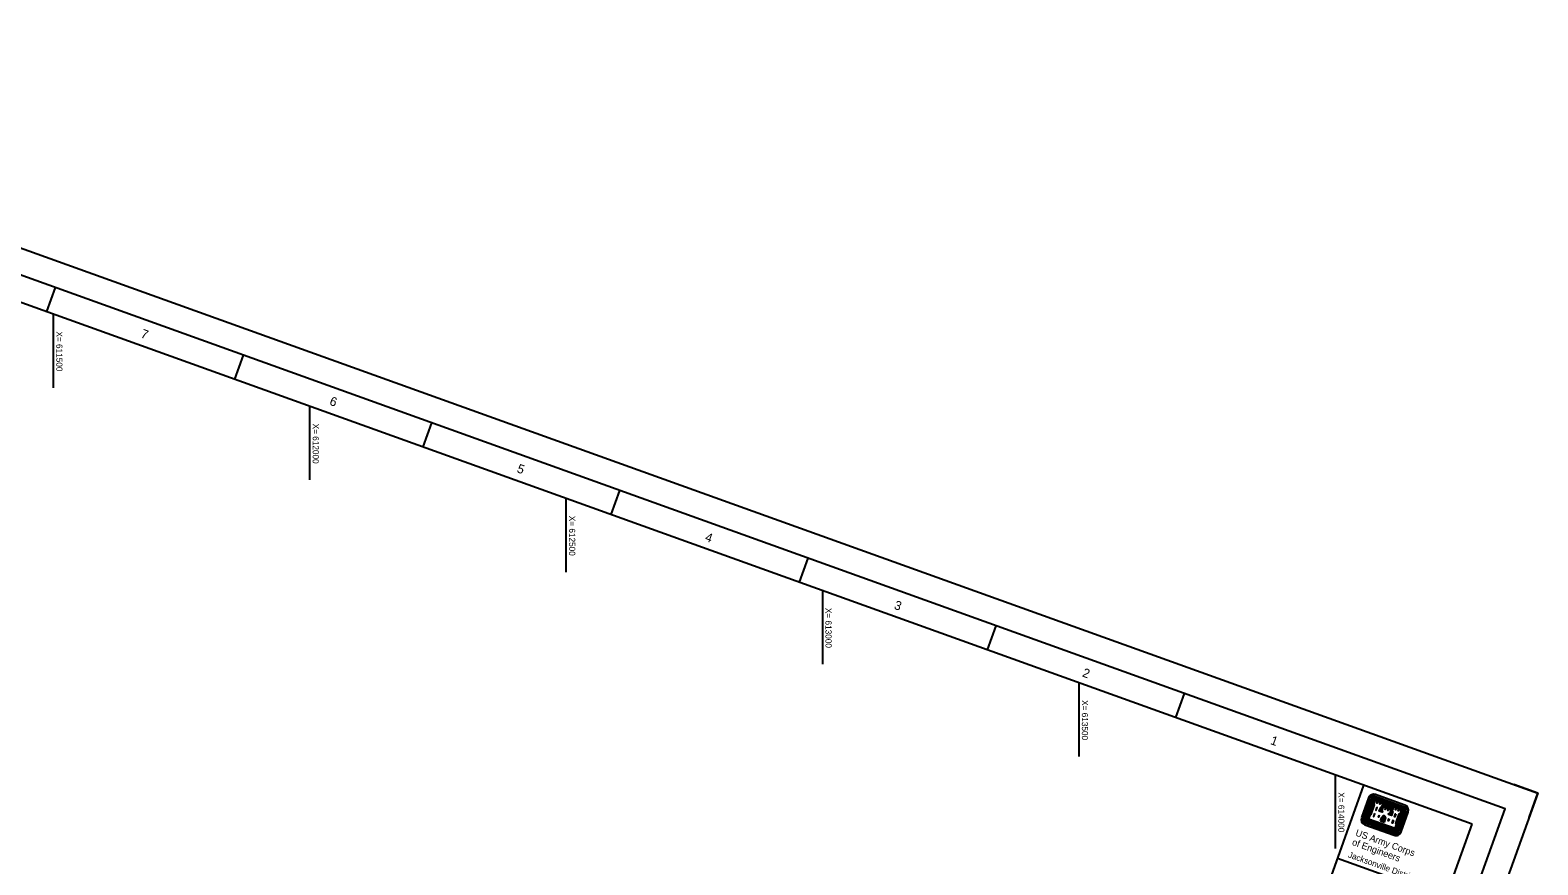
# Model space of a CAD drawing. Extents: x 609104 to 614395, y 782051 to 786739.
# Drawn here: x 611454 to 614395, y 785111 to 786739 of the extents above; entities that cross this region are included whole.
import ezdxf

# ---------------------------------------------------------------- set-up
doc = ezdxf.new("R2010")
doc.units = 0
for name, color, linetype in [('G-ANNO-NPLT', 7, 'Continuous'), ('G-ANNO-TEXT-LOGO', 7, 'Continuous'), ('G-ANNO-TEXT-TTLB', 7, 'Continuous'), ('G-ANNO-TTLB', 7, 'Continuous'), ('V-TOPO-COOR-STAT', 7, 'Continuous')]:
    doc.layers.add(name, color=color, linetype=linetype)

msp = doc.modelspace()

# ---------------------------------------------------------------- linework, layer by layer
at = {"layer": 'G-ANNO-NPLT'}
msp.add_lwpolyline([(610254.1, 786738.7), (614394.6, 785250.1), (613244.3, 782050.6), (609103.8, 783539.2)], close=True, dxfattribs=at)
msp.add_lwpolyline([(614377.7, 785203), (614394.6, 785250.1), (614347.6, 785267)], dxfattribs=at)
at = {"layer": 'G-ANNO-TEXT-LOGO'}
for p, q in [((614064.5, 785241.2), (614050.6, 785202.6)), ((614053.7, 785201.5), (614067.5, 785240.1)), ((614070.8, 785238.9), (614056.9, 785200.3)), ((614071.7, 785238.6), (614057.8, 785200)), ((614072.4, 785238.3), (614058.5, 785199.7)), ((614073.3, 785238), (614059.4, 785199.4)), ((614074.1, 785237.7), (614060.2, 785199.1)), ((614075, 785237.4), (614061.2, 785199.1)), ((614075.7, 785237.1), (614062.2, 785199.7)), ((614073.4, 785228.7), (614066.3, 785209)), ((614074, 785227.6), (614067.5, 785209.6)), ((614132, 785217.5), (614074.8, 785238.1)), ((614132.3, 785218.4), (614075.1, 785239)), ((614132.6, 785219.1), (614075.4, 785239.7)), ((614132.9, 785220), (614075.7, 785240.6)), ((614133.2, 785220.8), (614076, 785241.4)), ((614077.1, 785244.6), (614134.3, 785224)), ((614135.4, 785227), (614078.2, 785247.6)), ((614092.6, 785225.3), (614110.1, 785219)), ((614092.9, 785226.2), (614110.4, 785219.9)), ((614093.2, 785226.9), (614110.7, 785220.6)), ((614093.5, 785227.8), (614111, 785221.5)), ((614093.8, 785228.6), (614111.3, 785222.3)), ((614094.1, 785229.4), (614111.6, 785223.1)), ((614094.4, 785230.2), (614111.9, 785223.9)), ((614115.4, 785171.3), (614058.2, 785191.9)), ((614116.6, 785174.6), (614059.4, 785195.2)), ((614116.8, 785175.4), (614059.6, 785196)), ((614117.1, 785176.2), (614059.9, 785196.8)), ((614117.5, 785177.1), (614060.2, 785197.6)), ((614117.7, 785177.8), (614060.5, 785198.4)), ((614117.7, 785178.8), (614061.2, 785199.1)), ((614117.2, 785179.9), (614062.2, 785199.7)), ((614088, 785196.7), (614090.2, 785203)), ((614088, 785196.7), (614095.5, 785194)), ((614088.7, 785196.4), (614091, 785202.8)), ((614089.6, 785196.1), (614091.8, 785202.4)), ((614090.4, 785195.8), (614092.7, 785202.1)), ((614091.2, 785195.6), (614093.4, 785201.9)), ((614092.3, 785195.2), (614094.6, 785201.5)), ((614093, 785194.9), (614095.3, 785201.2)), ((614093.9, 785194.6), (614096.2, 785200.9)), ((614094.7, 785194.3), (614097, 785200.6)), ((614095.5, 785194), (614097.8, 785200.3)), ((614130.7, 785217.4), (614117.2, 785179.9)), ((614131.4, 785217.1), (614117.7, 785178.8)), ((614132.3, 785216.8), (614118.4, 785178.2)), ((614133.1, 785216.5), (614119.2, 785177.9)), ((614125.9, 785208.9), (614119.5, 785190.9)), ((614133.9, 785216.2), (614120, 785177.7)), ((614127, 785209.3), (614120, 785189.8)), ((614134.7, 785215.9), (614120.8, 785177.3)), ((614135.6, 785215.6), (614121.7, 785177)), ((614138.8, 785214.5), (614124.9, 785175.9)), ((614128, 785174.8), (614141.9, 785213.4)), ((614057.1, 785188.8), (614114.3, 785168.2))]:
    msp.add_line(p, q, dxfattribs=at)
for points in [[(614076.4, 785236.9), (614073.7, 785229.5), (614074.7, 785227.3), (614068.3, 785209.3), (614066.1, 785208.2), (614063.1, 785200), (614116.7, 785180.7), (614119.7, 785188.9), (614118.6, 785191.2), (614125.1, 785209.2), (614127.3, 785210.2), (614130, 785217.6), (614123, 785220.2), (614117.5, 785222.1), (614112.4, 785223.9), (614109.7, 785216.5), (614111, 785214.3), (614108.6, 785207.7), (614104.6, 785209.1), (614104.9, 785209.8), (614107.2, 785210.8), (614109.8, 785218.2), (614102.8, 785220.7), (614097.3, 785222.7), (614092.3, 785224.5), (614089.7, 785217.1), (614090.8, 785214.8), (614090.5, 785214.2), (614086.6, 785215.6), (614088.9, 785222.2), (614091.2, 785223.2), (614093.9, 785230.6), (614086.8, 785233.2), (614081.4, 785235.1), (614076.4, 785236.9)], [(614076.8, 785235.8), (614074.6, 785229.6), (614075.7, 785227.3), (614069, 785208.6), (614066.7, 785207.6), (614064.2, 785200.6), (614116.3, 785181.9), (614118.8, 785188.8), (614117.6, 785191.2), (614124.3, 785209.8), (614126.7, 785210.8), (614129, 785217), (614123.9, 785218.9), (614122.8, 785216), (614122.4, 785216.1), (614123.4, 785219), (614118.4, 785220.8), (614117.4, 785217.9), (614117, 785218.1), (614118, 785221), (614113, 785222.8), (614110.7, 785216.6), (614111.8, 785214.3), (614109.1, 785206.7), (614103.6, 785208.6), (614104.3, 785210.4), (614106.6, 785211.5), (614108.8, 785217.7), (614103.7, 785219.5), (614102.7, 785216.6), (614102.3, 785216.8), (614103.3, 785219.7), (614098.2, 785221.5), (614097.2, 785218.6), (614096.7, 785218.7), (614097.8, 785221.7), (614092.8, 785223.5), (614090.6, 785217.2), (614091.6, 785214.9), (614091, 785213.2), (614085.5, 785215.1), (614088.3, 785222.7), (614090.6, 785223.8), (614092.8, 785230), (614087.8, 785231.8), (614086.8, 785228.9), (614086.3, 785229.1), (614087.4, 785232), (614082.3, 785233.8), (614081.2, 785230.9), (614080.9, 785231), (614081.9, 785234), (614076.8, 785235.8)], [(614080.9, 785222.9), (614079, 785217.5), (614079.5, 785217.3), (614081.5, 785222.7), (614080.9, 785222.9)], [(614090.3, 785221.8), (614089.6, 785221.5), (614087.7, 785216.1), (614089.5, 785215.5), (614088.7, 785217.2), (614090.4, 785221.9)], [(614076.4, 785210.4), (614074.4, 785204.9), (614075, 785204.7), (614077, 785210.2), (614076.4, 785210.4)], [(614085.1, 785207.3), (614083.7, 785203.5), (614084.2, 785203.3), (614085.5, 785207.1), (614085.1, 785207.3)], [(614104.5, 785200.3), (614103.1, 785196.5), (614102.6, 785196.7), (614104, 785200.5), (614104.5, 785200.3)], [(614109.7, 785214.8), (614110, 785214.2), (614108, 785208.8), (614106.3, 785209.4), (614107.9, 785210.3), (614109.6, 785215)], [(614113, 785197.3), (614111, 785191.7), (614110.6, 785191.9), (614112.6, 785197.4), (614113, 785197.3)], [(614117.5, 785209.8), (614115.6, 785204.3), (614115.1, 785204.5), (614117.1, 785210), (614117.5, 785209.8)]]:
    msp.add_lwpolyline(points, dxfattribs=at)
for centre, major_axis, start_param, end_param in [((614074.6, 785237.6), (10.1, -3.6), 1.57078, 3.141576), ((614074.6, 785237.6), (7.05, -2.53), 1.57078, 3.141576), ((614074.6, 785237.6), (3.78, -1.36), 1.57078, 3.141576), ((614074.6, 785237.6), (2.96, -1.07), 1.57078, 3.141576), ((614074.6, 785237.6), (2.15, -0.77), 1.57078, 3.141576), ((614074.6, 785237.6), (1.33, -0.48), 1.57078, 3.141576), ((614074.6, 785237.6), (0.513, -0.185), 1.57078, 3.141576), ((614131.7, 785217), (2.15, -0.77), 6.283169, 7.853965), ((614131.7, 785217), (2.96, -1.07), 6.283169, 7.853965), ((614131.7, 785217), (3.78, -1.36), 6.283169, 7.853965), ((614131.7, 785217), (7.05, -2.53), 6.28317, 7.853966), ((614131.7, 785217), (10.1, -3.6), 6.283169, 7.853965), ((614060.7, 785198.9), (-10.1, 3.6), 6.28317, 7.853966), ((614060.7, 785198.9), (-7.05, 2.53), 6.28317, 7.853966), ((614060.7, 785198.9), (-3.78, 1.36), 6.28317, 7.853966), ((614060.7, 785198.9), (-2.96, 1.07), 6.28317, 7.853966), ((614060.7, 785198.9), (-2.15, 0.77), 6.28317, 7.853966), ((614060.7, 785198.9), (-1.33, 0.48), 6.28317, 7.853966), ((614060.7, 785198.9), (-0.513, 0.185), 6.28317, 7.853966), ((614095.2, 785200.7), (-5.23, 1.88), 4.985832, 6.214359), ((614095.2, 785200.7), (-4.41, 1.59), 4.947465, 6.21436), ((614095.2, 785200.7), (-3.59, 1.29), 4.947465, 6.21436), ((614095.2, 785200.7), (-2.78, 1), 4.947465, 6.21436), ((614095.2, 785200.7), (-1.96, 0.7), 4.947465, 6.214359), ((614092.4, 785201.8), (1.96, -0.7), 0.068794, 1.335689), ((614092.4, 785201.8), (2.78, -1), 0.068794, 1.335689), ((614092.4, 785201.8), (3.59, -1.29), 0.068795, 1.335689), ((614092.4, 785201.8), (4.41, -1.59), 0.068795, 1.335689), ((614092.4, 785201.8), (5.23, -1.88), 0.068795, 1.29842), ((614131.7, 785217), (0.513, -0.185), 6.283169, 7.853965), ((614131.7, 785217), (1.33, -0.48), 6.283169, 7.853965), ((614117.9, 785178.4), (10.1, -3.6), 4.712373, 6.28317), ((614117.9, 785178.4), (-7.05, 2.53), 1.570781, 3.141577), ((614117.9, 785178.4), (3.78, -1.36), 4.712373, 6.28317), ((614117.9, 785178.4), (2.96, -1.07), 4.712373, 6.28317), ((614117.9, 785178.4), (2.15, -0.77), 4.712373, 6.28317), ((614117.9, 785178.4), (1.33, -0.48), 4.712373, 6.28317), ((614117.9, 785178.4), (0.513, -0.185), 4.712373, 6.28317)]:
    msp.add_ellipse(centre, major_axis=major_axis, ratio=0.99964, start_param=start_param, end_param=end_param, dxfattribs=at)
at = {"layer": 'G-ANNO-TTLB'}
for p, q in [((611502.9, 786236.6), (611486, 786189.6)), ((611869.9, 786104.7), (611853, 786057.6)), ((612236.9, 785972.7), (612220, 785925.7)), ((612603.9, 785840.8), (612587, 785793.7)), ((612970.9, 785708.8), (612954, 785661.8)), ((613337.9, 785576.9), (613321, 785529.8)), ((613704.9, 785444.9), (613688, 785397.9)), ((614054.9, 785266), (612972.3, 782254.7)), ((614003.8, 785123.6), (614215.5, 785047.5))]:
    msp.add_line(p, q, dxfattribs=at)
for points in [[(609167.8, 783569.4), (613214.2, 782114.6), (614330.7, 785220), (610284.3, 786674.7)], [(614266.7, 785189.8), (610385, 786585.4), (609302.3, 783574.1), (613184.1, 782178.5)]]:
    msp.add_lwpolyline(points, close=True, dxfattribs=at)
at = {"layer": 'V-TOPO-COOR-STAT'}
for p, q in [((611500, 786041.1), (611500, 786184.5)), ((612000, 785861.3), (612000, 786004.8)), ((612500, 785681.5), (612500, 785825)), ((613000, 785501.8), (613000, 785645.2)), ((613500, 785322), (613500, 785465.5)), ((614000, 785142.2), (614000, 785285.7))]:
    msp.add_line(p, q, dxfattribs=at)

# ---------------------------------------------------------------- texts
at = {"layer": 'G-ANNO-TEXT-TTLB'}
for s, height, p in [('US Army Corps', 13.086, (614037.8, 785168)), ('Jacksonville District', 11.9, (614023.6, 785125.6)), ('of Engineers', 13.086, (614031.2, 785149.7))]:
    msp.add_text(s, height=height, rotation=340.2251, dxfattribs=at).set_placement(p)
at = {"layer": 'G-ANNO-TTLB'}
for s, p in [('7', (611668.8, 786139.8)), ('6', (612036.9, 786008.2)), ('5', (612402.4, 785876.7)), ('4', (612769.2, 785742.9)), ('3', (613137.8, 785610.4)), ('2', (613504.9, 785478.4)), ('1', (613871.8, 785346.5))]:
    msp.add_text(s, height=17.5, rotation=340.2251, dxfattribs=at).set_placement(p)
at = {"layer": 'V-TOPO-COOR-STAT'}
for s, p in [('X= 611500', (611505.4, 786151)), ('X= 612000', (612005.4, 785971.2)), ('X= 612500', (612505.4, 785791.4)), ('X= 613000', (613005.4, 785611.7)), ('X= 613500', (613505.4, 785431.9)), ('X= 614000', (614005.4, 785252.1))]:
    msp.add_text(s, height=12, rotation=270, dxfattribs=at).set_placement(p)

doc.saveas('drawing.dxf')
